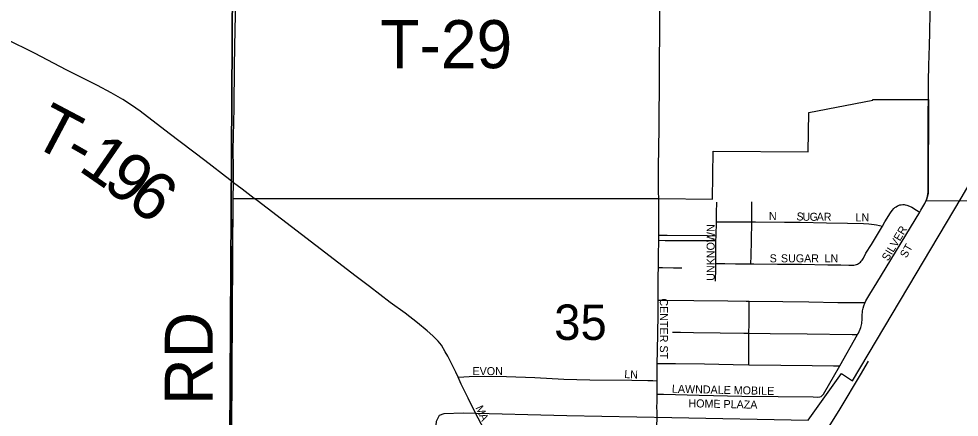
# Model space of a CAD drawing. Extents: x 1443599 to 1910620, y 1028088 to 1361369.
# Drawn here: x 1608527 to 1614403, y 1223049 to 1225536 of the extents above; entities that cross this region are included whole.
import ezdxf

# ---------------------------------------------------------------- set-up
doc = ezdxf.new("R2010")
doc.units = 0
for name, color, linetype in [('GM_X_City_Street', 7, 'Continuous'), ('GM_X_City_Street_Text', 7, 'Continuous'), ('GM_X_Corporation', 7, 'Continuous'), ('GM_X_Minor_River', 7, 'Continuous'), ('GM_X_Section', 7, 'Continuous'), ('GM_X_Section_Text', 7, 'Continuous'), ('GM_X_Township_Road', 7, 'Continuous'), ('GM_X_Township_Road_Text', 7, 'Continuous')]:
    doc.layers.add(name, color=color, linetype=linetype)

msp = doc.modelspace()

# ---------------------------------------------------------------- linework, layer by layer
at = {"layer": 'GM_X_City_Street'}
for points in [[(1611206.6, 1223429.2), (1611191.7, 1223456.5), (1611167.2, 1223498.1), (1611158, 1223511.2), (1611148, 1223523.6), (1611114.6, 1223557.5), (1611078.7, 1223588.2), (1611017.3, 1223638.2), (1610940.2, 1223698.3), (1610847.8, 1223765.6), (1610717.3, 1223863.9), (1610626.3, 1223933.1), (1610444.8, 1224072.5), (1610016.9, 1224400.7), (1609997.6, 1224415)], [(1612526.1, 1224186.1), (1612526.4, 1224204.2), (1612525.9, 1224285.9), (1612525.8, 1224333.5), (1612525.3, 1224382.9), (1612525.5, 1224411.3)], [(1612885.9, 1224267.9), (1612886.2, 1224275.7), (1612885.8, 1224324.9), (1612888.4, 1224390.3)], [(1613106.6, 1224268.4), (1613106.8, 1224297), (1613106.8, 1224377.4), (1613106.4, 1224393.4)], [(1614157, 1224329.4), (1614163.7, 1224340.4), (1614189, 1224382.7), (1614197, 1224401.7)], [(1613815, 1223764.1), (1613820, 1223774.5), (1613844.6, 1223817.6), (1613887.9, 1223888.2), (1614157, 1224329.4)], [(1613922.6, 1224241.7), (1613939, 1224269.3), (1613973.4, 1224325.5), (1613983.1, 1224339.4), (1613994.6, 1224352.2), (1614001.3, 1224358.3), (1614008.1, 1224363.1), (1614017.2, 1224368.1), (1614023.7, 1224371), (1614032.8, 1224373.8), (1614040.8, 1224375.3), (1614050.7, 1224376.2), (1614058.3, 1224375.8), (1614066.2, 1224374.7), (1614075.3, 1224372.7), (1614091.5, 1224366.9), (1614106.7, 1224359.4), (1614135.3, 1224342.4), (1614157, 1224329.4)], [(1612883.4, 1224181.6), (1612885.9, 1224267.9)], [(1612885.9, 1224267.9), (1612949.1, 1224268), (1613106.6, 1224268.4)], [(1613101.8, 1224006.2), (1613102.9, 1224055.5), (1613105.1, 1224152), (1613106.6, 1224268.4)], [(1613101.8, 1224006.2), (1613120.2, 1224006), (1613268.3, 1224003.6), (1613416.5, 1224003.3), (1613581.2, 1224000.3), (1613663.6, 1223999.9), (1613712.9, 1223997.4), (1613729, 1223997.4), (1613744.9, 1223998.7), (1613752.9, 1224000.3), (1613760.3, 1224002.1), (1613766.8, 1224004.4), (1613774.4, 1224008.1), (1613780.6, 1224012.3), (1613786.5, 1224017), (1613791.3, 1224022), (1613796.3, 1224028.8), (1613804.4, 1224042.5), (1613819.9, 1224071.9), (1613854.6, 1224127.8), (1613922.6, 1224241.7)], [(1613106.6, 1224268.4), (1613130, 1224268.5), (1613311, 1224267.4), (1613409.8, 1224266.4), (1613574.2, 1224262.2), (1613705.8, 1224260.4), (1613804.7, 1224258.4), (1613837.7, 1224256.5), (1613870.7, 1224252), (1613887.1, 1224248.8), (1613922.6, 1224241.7)], [(1612523.7, 1223983.9), (1612522.9, 1224026.9), (1612524, 1224058.8), (1612525.6, 1224153.3)], [(1612525.6, 1224153.3), (1612526.1, 1224186.1)], [(1612525.6, 1224153.3), (1612565.2, 1224152.5), (1612774.3, 1224151.9), (1612817.4, 1224151.8), (1612883, 1224151.7)], [(1612526.1, 1224186.1), (1612578.1, 1224185.5), (1612831, 1224182.3), (1612883.4, 1224181.6)], [(1612883, 1224151.7), (1612883.3, 1224177.2), (1612883.4, 1224181.6)], [(1612882.9, 1224008.2), (1612883, 1224029.6), (1612882.6, 1224111.7), (1612883, 1224151.7)], [(1612521.8, 1223779.9), (1612521, 1223827.7), (1612521, 1223932.3), (1612523.7, 1223983.9)], [(1612523.7, 1223983.9), (1612548.4, 1223983.4), (1612617.9, 1223982.1), (1612669.7, 1223982.2)], [(1612879.8, 1223898), (1612882.7, 1223980.2), (1612882.9, 1224008.2)], [(1612882.9, 1224008.2), (1612939.2, 1224007.5), (1613004.9, 1224006.7), (1613101.8, 1224006.2)], [(1612515.7, 1223383.2), (1612517.1, 1223461.6), (1612521.2, 1223688.6), (1612521.5, 1223736.7), (1612521.8, 1223779.9)], [(1612521.8, 1223779.9), (1612548.3, 1223779.6), (1612744.5, 1223777.5), (1612957.1, 1223774.7), (1613071.5, 1223773.4), (1613091.1, 1223773.1)], [(1613089.4, 1223573.2), (1613089.7, 1223630.7), (1613091, 1223727.6), (1613091, 1223743.6), (1613091.1, 1223773.1)], [(1613091.1, 1223773.1), (1613300.5, 1223770.4), (1613464, 1223768.2), (1613643.9, 1223764.9), (1613791.1, 1223764.3), (1613815, 1223764.1)], [(1613796.6, 1223662.9), (1613797, 1223679.4), (1613798.9, 1223712.5), (1613801.8, 1223728.7), (1613806.6, 1223744.4), (1613812.8, 1223759.7), (1613815, 1223764.1)], [(1613768.3, 1223564.2), (1613773.8, 1223573.7), (1613787.6, 1223608.5), (1613794.1, 1223633.1), (1613796.6, 1223662.9)], [(1612611.1, 1223578.6), (1612660.7, 1223579.3), (1612743.3, 1223578.1), (1612908.6, 1223576.4), (1613057.3, 1223573.7), (1613089.4, 1223573.2)], [(1613088.1, 1223376.4), (1613088.4, 1223420.9), (1613089.4, 1223573.2)], [(1613089.4, 1223573.2), (1613222.4, 1223571.4), (1613453.8, 1223568.2), (1613734.7, 1223564.6), (1613768.3, 1223564.2)], [(1613656.8, 1223370.1), (1613768.3, 1223564.2)], [(1611271.5, 1223298.2), (1611257, 1223329.6), (1611228.2, 1223388.2), (1611206.6, 1223429.2)], [(1613358.2, 1221746.6), (1613357.3, 1221847.3), (1613360.9, 1222127), (1613363.5, 1222274.9), (1613364, 1222488.6), (1613364.3, 1222537.9), (1613367.4, 1222570.7), (1613373, 1222603.2), (1613376.8, 1222619.2), (1613381.7, 1222634.9), (1613394.3, 1222665.2), (1613417.4, 1222708.9), (1613459.6, 1222779.6), (1613659.6, 1223101.4), (1613786.8, 1223313.2), (1613837.1, 1223398.2)], [(1612514.9, 1223276.1), (1612514.8, 1223330.8), (1612515.7, 1223383.2)], [(1612515, 1223193.1), (1612555.7, 1223192.1), (1612778.2, 1223186.5), (1613045.6, 1223179.8), (1613271.6, 1223178.2), (1613491.2, 1223175.4), (1613518.1, 1223174.1), (1613532.3, 1223176), (1613539.4, 1223178.7), (1613547.1, 1223184), (1613554.8, 1223192.5), (1613656.8, 1223370.1)], [(1612515.7, 1223383.2), (1612547.5, 1223383.7), (1612563.9, 1223383.9), (1612629.7, 1223383.1), (1612810.6, 1223380.9), (1612991.5, 1223377.5), (1613088.1, 1223376.4)], [(1613088.1, 1223376.4), (1613287.6, 1223373.7), (1613484.9, 1223370.8), (1613616.6, 1223370.3), (1613656.8, 1223370.1)], [(1611271.5, 1223298.2), (1611308.2, 1223300.3), (1611341, 1223302.3), (1611435, 1223304.8), (1611573.2, 1223303.1), (1611752.2, 1223296.1), (1611931.4, 1223286.6), (1612095.2, 1223282.5), (1612357.8, 1223280.4), (1612456.3, 1223278.7), (1612489.1, 1223277.2), (1612514.9, 1223276.1)], [(1611555.3, 1222749.3), (1611511, 1222834), (1611471.2, 1222905.5), (1611416.1, 1223006.2), (1611378.4, 1223079), (1611334.6, 1223167), (1611291.4, 1223255.5), (1611271.5, 1223298.2)], [(1612515, 1223193.1), (1612514.9, 1223233), (1612514.9, 1223276.1)], [(1612512.8, 1222883.2), (1612512.7, 1222901.8), (1612513.2, 1222933.2), (1612513.4, 1222948.8), (1612513.3, 1222963.9), (1612513.7, 1222979.6), (1612514.4, 1223010.7), (1612515.1, 1223026.1), (1612514.9, 1223058), (1612514.7, 1223088.2), (1612514.5, 1223104.2), (1612515.1, 1223151.3), (1612515, 1223193.1)]]:
    msp.add_lwpolyline(points, dxfattribs=at)
at = {"layer": 'GM_X_Corporation'}
msp.add_lwpolyline([(1615152.7, 1219006.6), (1612518, 1219058.9), (1609881.5, 1219107.2), (1609892.7, 1220442.9), (1609842.8, 1220442.3), (1609866.2, 1224413.7), (1609997.6, 1224415), (1612525.5, 1224413.2), (1612860.9, 1224410.9), (1612865, 1224709.3), (1613458.7, 1224705), (1613464, 1224951.2), (1613862.7, 1225028.4), (1613862.8, 1225032.3), (1614210.7, 1225031.5), (1614209.5, 1224468.5), (1614208.2, 1224448.3), (1614205.5, 1224428.7), (1614197, 1224401.7), (1615200.1, 1224394.6)], dxfattribs=at)
at = {"layer": 'GM_X_Minor_River'}
msp.add_lwpolyline([(1611444.7, 1220885.3), (1611444.3, 1221099.7), (1611143.6, 1221684), (1611133, 1222970.4), (1611135.9, 1223023.6), (1611156.5, 1223062.1), (1611184.5, 1223072.3), (1611302.9, 1223075.5), (1611951.5, 1223059.9), (1612608.1, 1223046.3), (1613458.9, 1223029.6), (1613668.1, 1223322.5), (1613735.4, 1223275.2), (1614133, 1223943.6), (1614415.2, 1224415.6), (1614773.8, 1225028.6), (1614851.4, 1225117.5), (1614884, 1225151), (1614912.4, 1225172.5)], dxfattribs=at)
at = {"layer": 'GM_X_Section'}
for points in [[(1604553.9, 1225803.6), (1609861.1, 1225754.9), (1609830.1, 1220437.4), (1604565.2, 1220497.6)], [(1609861.1, 1225754.9), (1615202.5, 1225719.6), (1615157.1, 1220376.3), (1609876.1, 1220436.7), (1609830.1, 1220437.4)]]:
    msp.add_lwpolyline(points, close=True, dxfattribs=at)
at = {"layer": 'GM_X_Township_Road'}
for points in [[(1609868.2, 1224512.1), (1609844.4, 1224530.5), (1609688.7, 1224650.8), (1609467.1, 1224820), (1609284.8, 1224959.6), (1609231.3, 1224997.5), (1609175.8, 1225032.4), (1609104.7, 1225073.3), (1609017.5, 1225118.9), (1608827.9, 1225216.3), (1608623.9, 1225321.5), (1608448, 1225409.5), (1608171.9, 1225553.7), (1607968.5, 1225660), (1607837.3, 1225727.4), (1607823.3, 1225735.7), (1607812.1, 1225743.3), (1607804.5, 1225751.3), (1607794.1, 1225768.7)], [(1609867.8, 1224607.2), (1609866.7, 1224716.7), (1609871.6, 1224979.1), (1609873.9, 1225241.7), (1609876.1, 1225356.6), (1609878.8, 1225471.3), (1609880, 1225553.3), (1609881.7, 1225651.6), (1609883, 1225717.1), (1609883.2, 1225748.7)], [(1612524, 1224538.2), (1612524, 1224620.4), (1612525.1, 1224718.2), (1612527.3, 1224865.5), (1612527.9, 1224930.8), (1612528.7, 1224996.1), (1612529.2, 1225045.4), (1612530.4, 1225289.3), (1612532.6, 1225431), (1612532.5, 1225565.9), (1612535.8, 1225749.2)], [(1614210.7, 1225031.5), (1614211.1, 1225147.8), (1614213.4, 1225243.7), (1614217.7, 1225369), (1614220.1, 1225450), (1614221.2, 1225575.1), (1614223.7, 1225621.7), (1614222.6, 1225685.7), (1614223.8, 1225722.3)], [(1614197, 1224401.7), (1614202.5, 1224417.7), (1614205.5, 1224428.7), (1614207.6, 1224442.2), (1614208.9, 1224454.4), (1614209.6, 1224470.9), (1614208.6, 1224553.7), (1614209.7, 1224950.8), (1614210.7, 1225031.5)], [(1609868.2, 1224512.1), (1609868.5, 1224526.8), (1609867.9, 1224598.6), (1609867.8, 1224607.2)], [(1609866.2, 1224413.7), (1609868.2, 1224512.1)], [(1609997.6, 1224415), (1609922.4, 1224472.9), (1609868.2, 1224512.1)], [(1612525.5, 1224411.3), (1612524.1, 1224457.3), (1612524, 1224538.2)], [(1609842.8, 1220442.3), (1609838.9, 1220766.1), (1609840, 1220946.6), (1609840.4, 1221176.4), (1609841.4, 1221357), (1609840.4, 1221537.5), (1609844.5, 1221752.6), (1609846.2, 1221946.1), (1609846.1, 1222106.8), (1609846, 1222294.8), (1609847.7, 1222636.1), (1609852.9, 1223141.7), (1609856.5, 1223346.2), (1609856.4, 1223474), (1609858.1, 1223720.4), (1609859.8, 1223932.1), (1609864.2, 1224181), (1609865.9, 1224390.3), (1609866.2, 1224413.7)]]:
    msp.add_lwpolyline(points, dxfattribs=at)

# ---------------------------------------------------------------- texts
at = {"layer": 'GM_X_City_Street_Text'}
for s, rotation, p in [('N', 0.00001, (1613214.1, 1224279.5)), ('S', 354.2269, (1613383.7, 1224279.3)), ('U', 359.53113, (1613423.8, 1224275.5)), ('G', 359.99285, (1613468.2, 1224275.1)), ('A', 359.99285, (1613512.2, 1224275.1)), ('R', 359.99406, (1613556.2, 1224275.1)), ('LN', 0.00001, (1613755.3, 1224270.7)), ('UNKNOWN', 90, (1612874.7, 1223900.5)), ('SILVER', 59.23947, (1613958.4, 1224019.7)), ('ST', 60.25679, (1614072.6, 1224038.5)), ('S', 0.00001, (1613218.5, 1224015.6)), ('SUGAR', 0.00001, (1613288.9, 1224015.6)), ('LN', 0.00001, (1613561.7, 1224015.5)), ('CENTER ST', 270, (1612532.7, 1223790.5)), ('EVON', 0.00001, (1611361.7, 1223311.5)), ('L', 355.46093, (1612308.7, 1223293.9)), ('N', 358.1706, (1612346.3, 1223291)), ('LAWNDALE MOBILE', 358.72787, (1612607.3, 1223201.5)), ('HOME PLAZA', 358.69934, (1612710.6, 1223111.2)), ('M', 294.52837, (1611379.1, 1223108)), ('A', 295.09961, (1611401.2, 1223059.5))]:
    msp.add_text(s, height=50, rotation=rotation, dxfattribs=at).set_placement(p)
at = {"layer": 'GM_X_Section_Text'}
msp.add_text('35', height=221, rotation=0.00001, dxfattribs=at).set_placement((1611872.1, 1223531.2))
at = {"layer": 'GM_X_Township_Road_Text'}
for s, rotation, p in [('T-29', 0.00001, (1610785.3, 1225227.8)), ('T', 332.15264, (1608594.1, 1224755.1)), ('-', 330.33355, (1608790.3, 1224651.5)), ('1', 325.39339, (1608891.5, 1224594.2)), ('9', 323.25292, (1609041.2, 1224490.9)), ('6', 322.98127, (1609189, 1224380.6)), ('RD', 90, (1609739, 1223126.1))]:
    msp.add_text(s, height=300, rotation=rotation, dxfattribs=at).set_placement(p)

doc.saveas('drawing.dxf')
